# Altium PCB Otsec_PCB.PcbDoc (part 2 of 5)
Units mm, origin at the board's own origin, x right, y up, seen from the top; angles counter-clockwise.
Board outline 170 x 120 mm, 3 copper layers (Top Layer, Internal Plane 1, Bottom Layer), stack 1.608 mm thick; 1624 components, 0 nets, 5478 pads, 0 vias.
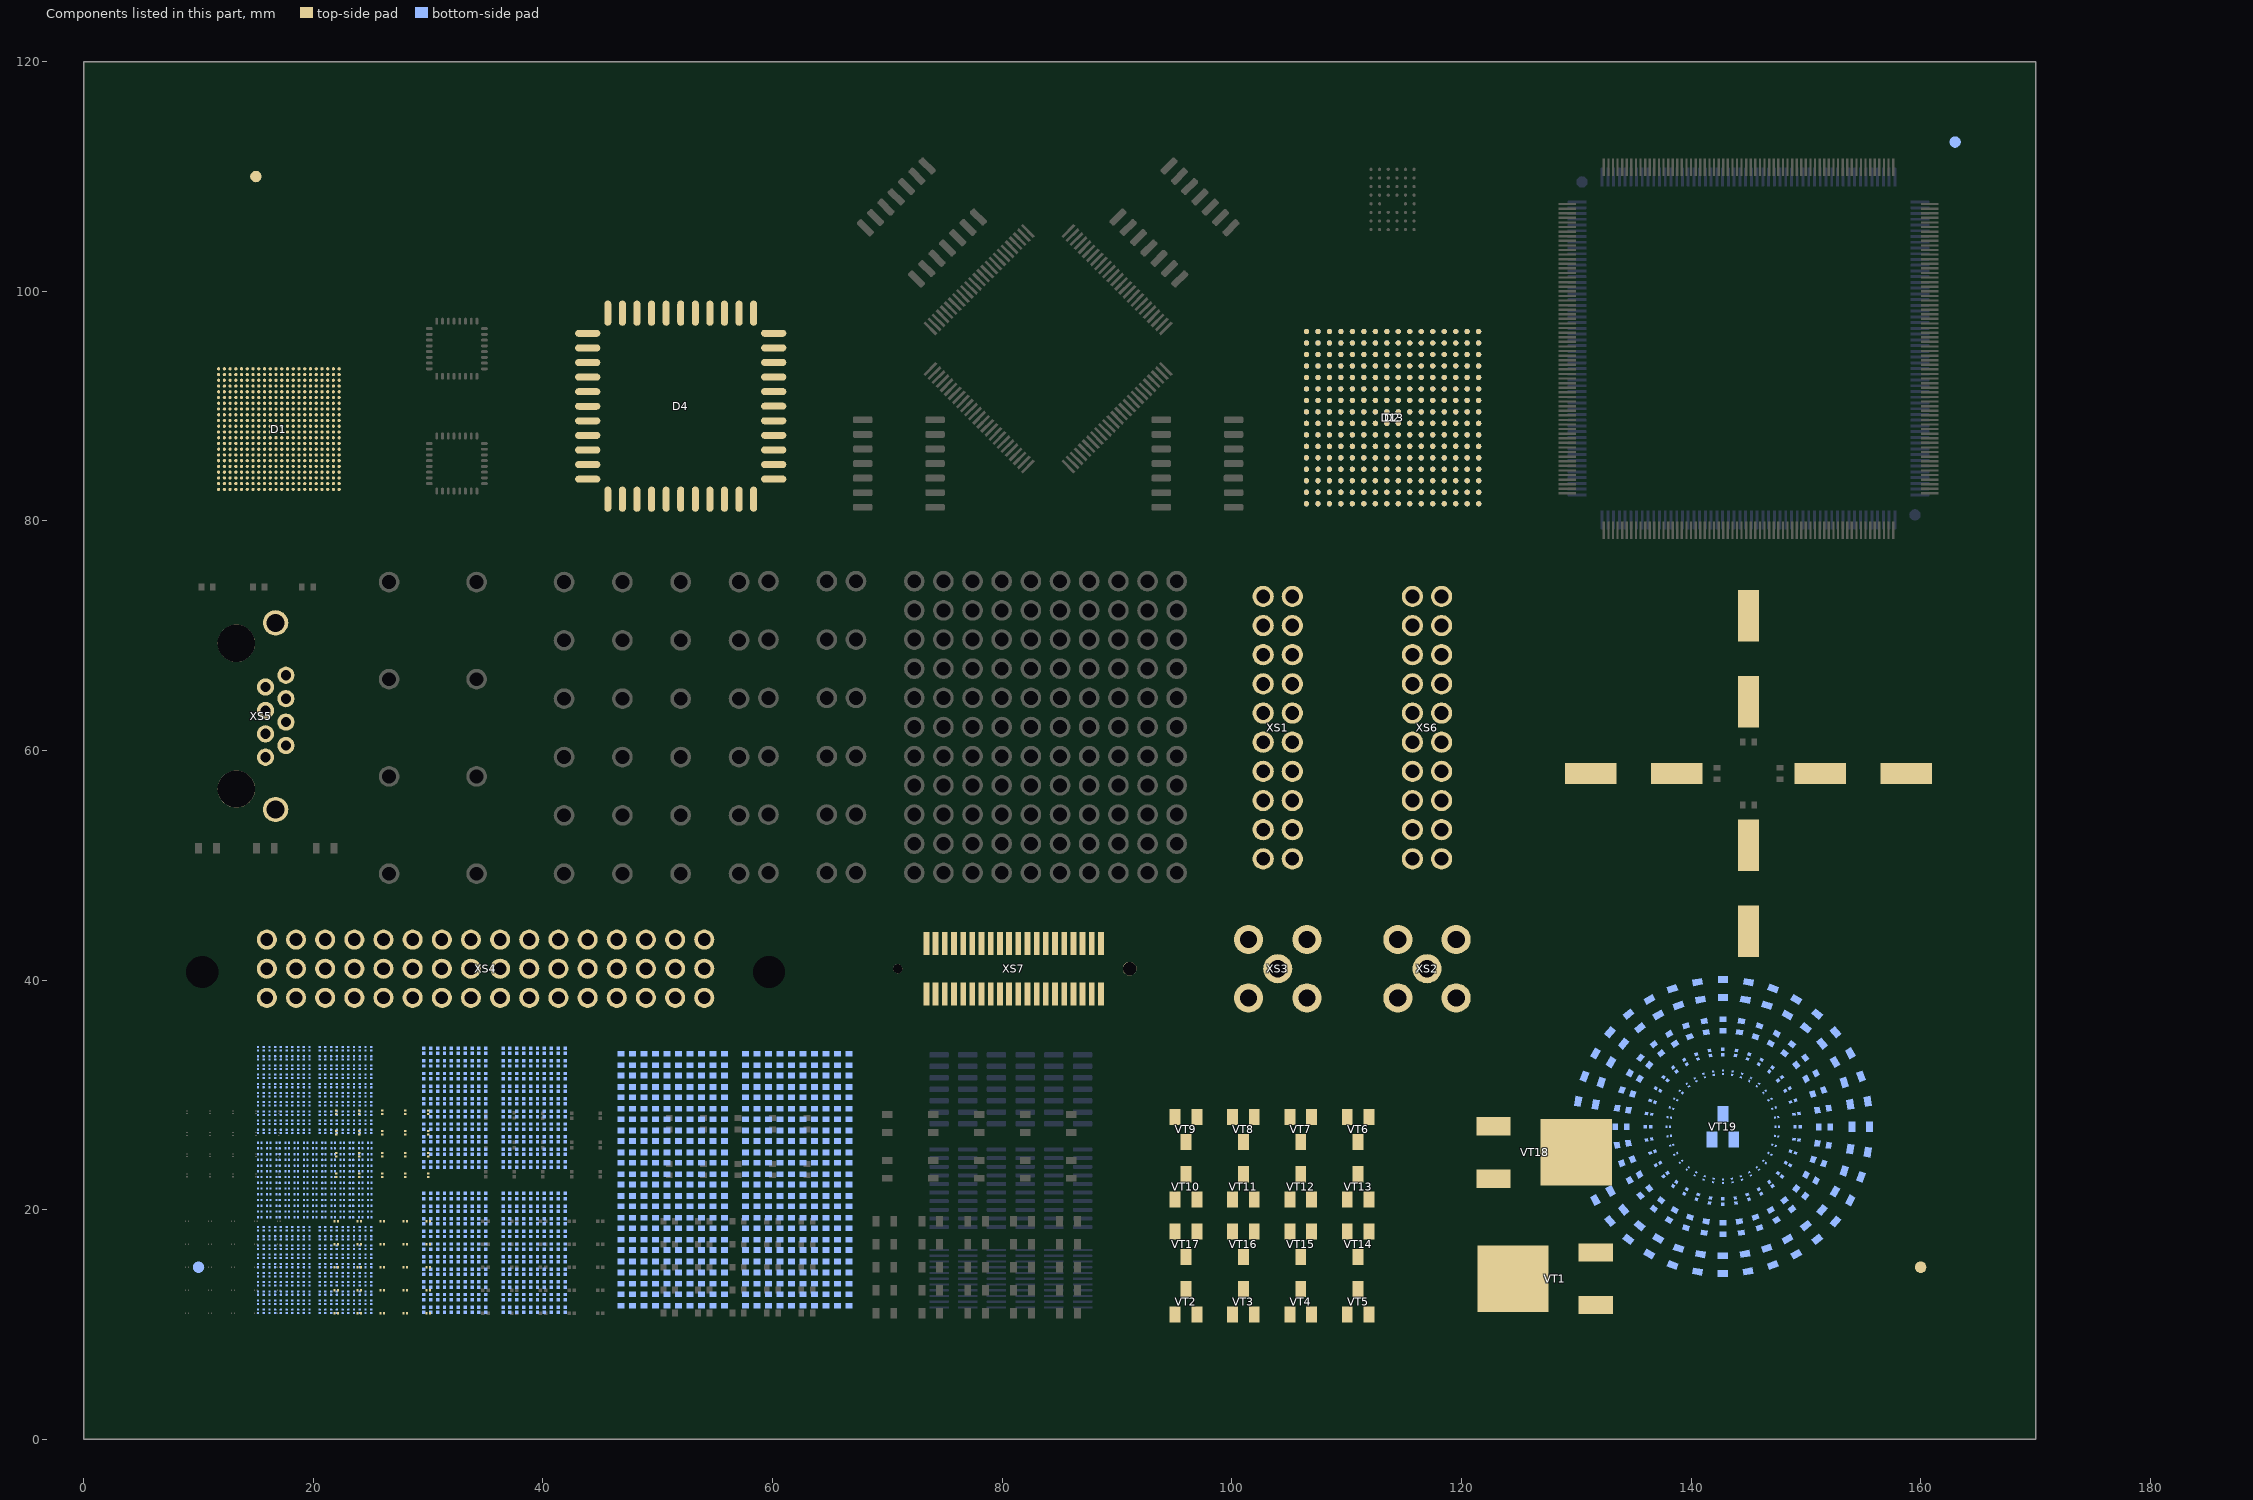
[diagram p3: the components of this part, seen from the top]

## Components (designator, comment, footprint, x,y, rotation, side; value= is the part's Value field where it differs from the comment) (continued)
R375_2 "*" R0201_nosilk 35.025,12.4 r90 bottom
R375_2_1 "*" R0201_nosilk 41.925,12.4 r90 bottom
R376 "*" R0201_nosilk 33.225,32.75 r90 bottom
R376_1 "*" R0201_nosilk 40.125,32.75 r90 bottom
R376_2 "*" R0201_nosilk 33.225,20.1 r90 bottom
R376_2_1 "*" R0201_nosilk 40.125,20.1 r90 bottom
R377 "*" R0201_nosilk 34.425,32.75 r90 bottom
R377_1 "*" R0201_nosilk 41.325,32.75 r90 bottom
R377_2 "*" R0201_nosilk 34.425,20.1 r90 bottom
R377_2_1 "*" R0201_nosilk 41.325,20.1 r90 bottom
R378 "*" R0201_nosilk 31.425,31.65 r90 bottom
R378_1 "*" R0201_nosilk 38.325,31.65 r90 bottom
R378_2 "*" R0201_nosilk 31.425,19 r90 bottom
R378_2_1 "*" R0201_nosilk 38.325,19 r90 bottom
R379 "*" R0201_nosilk 33.825,31.65 r90 bottom
R379_1 "*" R0201_nosilk 40.725,31.65 r90 bottom
R379_2 "*" R0201_nosilk 33.825,19 r90 bottom
R379_2_1 "*" R0201_nosilk 40.725,19 r90 bottom
R380 "*" R0201_nosilk 30.825,30.55 r90 bottom
R380_1 "*" R0201_nosilk 37.725,30.55 r90 bottom
R380_2 "*" R0201_nosilk 30.825,17.9 r90 bottom
R380_2_1 "*" R0201_nosilk 37.725,17.9 r90 bottom
R381 "*" R0201_nosilk 35.025,30.55 r90 bottom
R381_1 "*" R0201_nosilk 41.925,30.55 r90 bottom
R381_2 "*" R0201_nosilk 35.025,17.9 r90 bottom
R381_2_1 "*" R0201_nosilk 41.925,17.9 r90 bottom
R382 "*" R0201_nosilk 29.625,29.45 r90 bottom
R382_1 "*" R0201_nosilk 36.525,29.45 r90 bottom
R382_2 "*" R0201_nosilk 29.625,16.8 r90 bottom
R382_2_1 "*" R0201_nosilk 36.525,16.8 r90 bottom
R383 "*" R0201_nosilk 35.025,23.95 r90 bottom
R383_1 "*" R0201_nosilk 41.925,23.95 r90 bottom
R383_2 "*" R0201_nosilk 35.025,11.3 r90 bottom
R383_2_1 "*" R0201_nosilk 41.925,11.3 r90 bottom
R384 "*" R0201_nosilk 32.025,23.95 r90 bottom
R384_1 "*" R0201_nosilk 38.925,23.95 r90 bottom
R384_2 "*" R0201_nosilk 32.025,11.3 r90 bottom
R384_2_1 "*" R0201_nosilk 38.925,11.3 r90 bottom
R385 "*" R0201_nosilk 29.625,23.95 r90 bottom
R385_1 "*" R0201_nosilk 36.525,23.95 r90 bottom
R385_2 "*" R0201_nosilk 29.625,11.3 r90 bottom
R385_2_1 "*" R0201_nosilk 36.525,11.3 r90 bottom
R386 "*" R0201_nosilk 30.225,31.65 r90 bottom
R386_1 "*" R0201_nosilk 37.125,31.65 r90 bottom
R386_2 "*" R0201_nosilk 30.225,19 r90 bottom
R386_2_1 "*" R0201_nosilk 37.125,19 r90 bottom
R387 "*" R0201_nosilk 32.025,31.65 r90 bottom
R387_1 "*" R0201_nosilk 38.925,31.65 r90 bottom
R387_2 "*" R0201_nosilk 32.025,19 r90 bottom
R387_2_1 "*" R0201_nosilk 38.925,19 r90 bottom
R388 "*" R0201_nosilk 32.625,31.65 r90 bottom
R388_1 "*" R0201_nosilk 39.525,31.65 r90 bottom
R388_2 "*" R0201_nosilk 32.625,19 r90 bottom
R388_2_1 "*" R0201_nosilk 39.525,19 r90 bottom
R389 "*" R0201_nosilk 32.625,30.55 r90 bottom
R389_1 "*" R0201_nosilk 39.525,30.55 r90 bottom
R389_2 "*" R0201_nosilk 32.625,17.9 r90 bottom
R389_2_1 "*" R0201_nosilk 39.525,17.9 r90 bottom
R390 "*" R0201_nosilk 33.225,30.55 r90 bottom
R390_1 "*" R0201_nosilk 40.125,30.55 r90 bottom
R390_2 "*" R0201_nosilk 33.225,17.9 r90 bottom
R390_2_1 "*" R0201_nosilk 40.125,17.9 r90 bottom
R391 "*" R0201_nosilk 30.225,29.45 r90 bottom
R391_1 "*" R0201_nosilk 37.125,29.45 r90 bottom
R391_2 "*" R0201_nosilk 30.225,16.8 r90 bottom
R391_2_1 "*" R0201_nosilk 37.125,16.8 r90 bottom
R392 "*" R0201_nosilk 32.625,29.45 r90 bottom
R392_1 "*" R0201_nosilk 39.525,29.45 r90 bottom
R392_2 "*" R0201_nosilk 32.625,16.8 r90 bottom
R392_2_1 "*" R0201_nosilk 39.525,16.8 r90 bottom
R393 "*" R0201_nosilk 34.425,23.95 r90 bottom
R393_1 "*" R0201_nosilk 41.325,23.95 r90 bottom
R393_2 "*" R0201_nosilk 34.425,11.3 r90 bottom
R393_2_1 "*" R0201_nosilk 41.325,11.3 r90 bottom
R394 "*" R0201_nosilk 32.625,23.95 r90 bottom
R394_1 "*" R0201_nosilk 39.525,23.95 r90 bottom
R394_2 "*" R0201_nosilk 32.625,11.3 r90 bottom
R394_2_1 "*" R0201_nosilk 39.525,11.3 r90 bottom
R395 "*" R0201_nosilk 31.425,23.95 r90 bottom
R395_1 "*" R0201_nosilk 38.325,23.95 r90 bottom
R395_2 "*" R0201_nosilk 31.425,11.3 r90 bottom
R395_2_1 "*" R0201_nosilk 38.325,11.3 r90 bottom
R396 "*" R0201_nosilk 33.825,32.75 r90 bottom
R396_1 "*" R0201_nosilk 40.725,32.75 r90 bottom
R396_2 "*" R0201_nosilk 33.825,20.1 r90 bottom
R396_2_1 "*" R0201_nosilk 40.725,20.1 r90 bottom
R397 "*" R0201_nosilk 34.425,31.65 r90 bottom
R397_1 "*" R0201_nosilk 41.325,31.65 r90 bottom
R397_2 "*" R0201_nosilk 34.425,19 r90 bottom
R397_2_1 "*" R0201_nosilk 41.325,19 r90 bottom
R398 "*" R0201_nosilk 35.025,31.65 r90 bottom
R398_1 "*" R0201_nosilk 41.925,31.65 r90 bottom
R398_2 "*" R0201_nosilk 35.025,19 r90 bottom
R398_2_1 "*" R0201_nosilk 41.925,19 r90 bottom
R399 "*" R0201_nosilk 33.825,30.55 r90 bottom
R399_1 "*" R0201_nosilk 40.725,30.55 r90 bottom
R399_2 "*" R0201_nosilk 33.825,17.9 r90 bottom
R399_2_1 "*" R0201_nosilk 40.725,17.9 r90 bottom
R400 "*" R0201_nosilk 34.425,30.55 r90 bottom
R400_1 "*" R0201_nosilk 41.325,30.55 r90 bottom
R400_2 "*" R0201_nosilk 34.425,17.9 r90 bottom
R400_2_1 "*" R0201_nosilk 41.325,17.9 r90 bottom
R401 "*" R0201_nosilk 31.425,29.45 r90 bottom
R401_1 "*" R0201_nosilk 38.325,29.45 r90 bottom
R401_2 "*" R0201_nosilk 31.425,16.8 r90 bottom
R401_2_1 "*" R0201_nosilk 38.325,16.8 r90 bottom
R402 "*" R0201_nosilk 32.025,29.45 r90 bottom
R402_1 "*" R0201_nosilk 38.925,29.45 r90 bottom
R402_2 "*" R0201_nosilk 32.025,16.8 r90 bottom
R402_2_1 "*" R0201_nosilk 38.925,16.8 r90 bottom
R403 "*" R0201_nosilk 33.825,23.95 r90 bottom
R403_1 "*" R0201_nosilk 40.725,23.95 r90 bottom
R403_2 "*" R0201_nosilk 33.825,11.3 r90 bottom
R403_2_1 "*" R0201_nosilk 40.725,11.3 r90 bottom
R404 "*" R0201_nosilk 33.225,23.95 r90 bottom
R404_1 "*" R0201_nosilk 40.125,23.95 r90 bottom
R404_2 "*" R0201_nosilk 33.225,11.3 r90 bottom
R404_2_1 "*" R0201_nosilk 40.125,11.3 r90 bottom
R405 "*" R0201_nosilk 30.825,23.95 r90 bottom
R405_1 "*" R0201_nosilk 37.725,23.95 r90 bottom
R405_2 "*" R0201_nosilk 30.825,11.3 r90 bottom
R405_2_1 "*" R0201_nosilk 37.725,11.3 r90 bottom
R406 "*" R0201_nosilk 35.025,32.75 r90 bottom
R406_1 "*" R0201_nosilk 41.925,32.75 r90 bottom
R406_2 "*" R0201_nosilk 35.025,20.1 r90 bottom
R406_2_1 "*" R0201_nosilk 41.925,20.1 r90 bottom
R407 "*" R0201_nosilk 29.625,30.55 r90 bottom
R407_1 "*" R0201_nosilk 36.525,30.55 r90 bottom
R407_2 "*" R0201_nosilk 29.625,17.9 r90 bottom
R407_2_1 "*" R0201_nosilk 36.525,17.9 r90 bottom
R408 "*" R0201_nosilk 30.225,30.55 r90 bottom
R408_1 "*" R0201_nosilk 37.125,30.55 r90 bottom
R408_2 "*" R0201_nosilk 30.225,17.9 r90 bottom
R408_2_1 "*" R0201_nosilk 37.125,17.9 r90 bottom
R409 "*" R0201_nosilk 32.625,32.75 r90 bottom
R409_1 "*" R0201_nosilk 39.525,32.75 r90 bottom
R409_2 "*" R0201_nosilk 32.625,20.1 r90 bottom
R409_2_1 "*" R0201_nosilk 39.525,20.1 r90 bottom
R410 "*" R0201_nosilk 30.825,29.45 r90 bottom
R410_1 "*" R0201_nosilk 37.725,29.45 r90 bottom
R410_2 "*" R0201_nosilk 30.825,16.8 r90 bottom
R410_2_1 "*" R0201_nosilk 37.725,16.8 r90 bottom
R411 "*" R0402_NOSILK 54.8,23.6 r90 bottom
R411_1 "*" R0402_NOSILK 65.65,23.6 r90 bottom
R412 "*" R0402_NOSILK 47.8,21.7 r90 bottom
R412_1 "*" R0402_NOSILK 58.65,21.7 r90 bottom
R413 "*" R0402_NOSILK 50.8,25.5 r90 bottom
R413_1 "*" R0402_NOSILK 61.65,25.5 r90 bottom
R414 "*" R0402_NOSILK 53.8,25.5 r90 bottom
R414_1 "*" R0402_NOSILK 64.65,25.5 r90 bottom
R415 "*" R0402_NOSILK 48.8,23.6 r90 bottom
R415_1 "*" R0402_NOSILK 59.65,23.6 r90 bottom
R416 "*" R0402_NOSILK 53.8,23.6 r90 bottom
R416_1 "*" R0402_NOSILK 64.65,23.6 r90 bottom
R417 "*" R0402_NOSILK 51.8,19.8 r90 bottom
R417_1 "*" R0402_NOSILK 62.65,19.8 r90 bottom
R418 "*" R0402_NOSILK 53.8,16 r90 bottom
R418_1 "*" R0402_NOSILK 64.65,16 r90 bottom
R418_1_1 "*" R0402_NOSILK 64.65,12.15 r90 bottom
R418_2 "*" R0402_NOSILK 53.8,12.15 r90 bottom
R419 "*" R0402_NOSILK 49.8,31.2 r90 bottom
R419_1 "*" R0402_NOSILK 60.65,31.2 r90 bottom
R420 "*" R0402_NOSILK 48.8,29.3 r90 bottom
R420_1 "*" R0402_NOSILK 59.65,29.3 r90 bottom
R421 "*" R0402_NOSILK 52.8,31.2 r90 bottom
R421_1 "*" R0402_NOSILK 63.65,31.2 r90 bottom
R422 "*" R0402_NOSILK 46.8,17.9 r90 bottom
R422_1 "*" R0402_NOSILK 57.65,17.9 r90 bottom
R422_1_1 "*" R0402_NOSILK 57.65,14.05 r90 bottom
R422_2 "*" R0402_NOSILK 46.8,14.05 r90 bottom
R423 "*" R0402_NOSILK 52.8,17.9 r90 bottom
R423_1 "*" R0402_NOSILK 63.65,17.9 r90 bottom
R423_1_1 "*" R0402_NOSILK 63.65,14.05 r90 bottom
R423_2 "*" R0402_NOSILK 52.8,14.05 r90 bottom
R424 "*" R0402_NOSILK 47.8,27.4 r90 bottom
R424_1 "*" R0402_NOSILK 58.65,27.4 r90 bottom
R425 "*" R0402_NOSILK 53.8,27.4 r90 bottom
R425_1 "*" R0402_NOSILK 64.65,27.4 r90 bottom
R426 "*" R0402_NOSILK 47.8,16 r90 bottom
R426_1 "*" R0402_NOSILK 58.65,16 r90 bottom
R426_1_1 "*" R0402_NOSILK 58.65,12.15 r90 bottom
R426_2 "*" R0402_NOSILK 47.8,12.15 r90 bottom
R427 "*" R0402_NOSILK 50.8,16 r90 bottom
R427_1 "*" R0402_NOSILK 61.65,16 r90 bottom
R427_1_1 "*" R0402_NOSILK 61.65,12.15 r90 bottom
R427_2 "*" R0402_NOSILK 50.8,12.15 r90 bottom
R428 "*" R0402_NOSILK 46.8,25.5 r90 bottom
R428_1 "*" R0402_NOSILK 57.65,25.5 r90 bottom
R429 "*" R0402_NOSILK 49.8,25.5 r90 bottom
R429_1 "*" R0402_NOSILK 60.65,25.5 r90 bottom
R430 "*" R0402_NOSILK 51.8,33.1 r90 bottom
R430_1 "*" R0402_NOSILK 62.65,33.1 r90 bottom
R431 "*" R0402_NOSILK 48.8,21.7 r90 bottom
R431_1 "*" R0402_NOSILK 59.65,21.7 r90 bottom
R432 "*" R0402_NOSILK 51.8,21.7 r90 bottom
R432_1 "*" R0402_NOSILK 62.65,21.7 r90 bottom
R433 "*" R0402_NOSILK 54.8,19.8 r90 bottom
R433_1 "*" R0402_NOSILK 65.65,19.8 r90 bottom
R434 "*" R0402_NOSILK 46.8,31.2 r90 bottom
R434_1 "*" R0402_NOSILK 57.65,31.2 r90 bottom
R435 "*" R0402_NOSILK 46.8,29.3 r90 bottom
R435_1 "*" R0402_NOSILK 57.65,29.3 r90 bottom
R436 "*" R0402_NOSILK 55.8,33.1 r90 bottom
R436_1 "*" R0402_NOSILK 66.65,33.1 r90 bottom
R437 "*" R0402_NOSILK 49.8,23.6 r90 bottom
R437_1 "*" R0402_NOSILK 60.65,23.6 r90 bottom
R438 "*" R0402_NOSILK 52.8,23.6 r90 bottom
R438_1 "*" R0402_NOSILK 63.65,23.6 r90 bottom
R439 "*" R0402_NOSILK 54.8,29.3 r90 bottom
R439_1 "*" R0402_NOSILK 65.65,29.3 r90 bottom
R440 "*" R0402_NOSILK 50.8,27.4 r90 bottom
R440_1 "*" R0402_NOSILK 61.65,27.4 r90 bottom
R441 "*" R0402_NOSILK 52.8,16 r90 bottom
R441_1 "*" R0402_NOSILK 63.65,16 r90 bottom
R441_1_1 "*" R0402_NOSILK 63.65,12.15 r90 bottom
R441_2 "*" R0402_NOSILK 52.8,12.15 r90 bottom
R442 "*" R0402_NOSILK 48.8,25.5 r90 bottom
R442_1 "*" R0402_NOSILK 59.65,25.5 r90 bottom
R443 "*" R0402_NOSILK 54.8,25.5 r90 bottom
R443_1 "*" R0402_NOSILK 65.65,25.5 r90 bottom
R444 "*" R0402_NOSILK 47.8,33.1 r90 bottom
R444_1 "*" R0402_NOSILK 58.65,33.1 r90 bottom
R445 "*" R0402_NOSILK 48.8,33.1 r90 bottom
R445_1 "*" R0402_NOSILK 59.65,33.1 r90 bottom
R446 "*" R0402_NOSILK 47.8,19.8 r90 bottom
R446_1 "*" R0402_NOSILK 58.65,19.8 r90 bottom
R447 "*" R0402_NOSILK 46.8,16 r90 bottom
R447_1 "*" R0402_NOSILK 57.65,16 r90 bottom
R447_1_1 "*" R0402_NOSILK 57.65,12.15 r90 bottom
R447_2 "*" R0402_NOSILK 46.8,12.15 r90 bottom
R448 "*" R0402_NOSILK 48.8,31.2 r90 bottom
R448_1 "*" R0402_NOSILK 59.65,31.2 r90 bottom
R449 "*" R0402_NOSILK 51.8,29.3 r90 bottom
R449_1 "*" R0402_NOSILK 62.65,29.3 r90 bottom
R450 "*" R0402_NOSILK 49.8,16 r90 bottom
R450_1 "*" R0402_NOSILK 60.65,16 r90 bottom
R450_1_1 "*" R0402_NOSILK 60.65,12.15 r90 bottom
R450_2 "*" R0402_NOSILK 49.8,12.15 r90 bottom
R451 "*" R0402_NOSILK 51.8,23.6 r90 bottom
R451_1 "*" R0402_NOSILK 62.65,23.6 r90 bottom
R452 "*" R0402_NOSILK 51.8,17.9 r90 bottom
R452_1 "*" R0402_NOSILK 62.65,17.9 r90 bottom
R452_1_1 "*" R0402_NOSILK 62.65,14.05 r90 bottom
R452_2 "*" R0402_NOSILK 51.8,14.05 r90 bottom
R453 "*" R0402_NOSILK 46.8,27.4 r90 bottom
R453_1 "*" R0402_NOSILK 57.65,27.4 r90 bottom
R454 "*" R0402_NOSILK 52.8,27.4 r90 bottom
R454_1 "*" R0402_NOSILK 63.65,27.4 r90 bottom
R455 "*" R0402_NOSILK 50.8,21.7 r90 bottom
R455_1 "*" R0402_NOSILK 61.65,21.7 r90 bottom
R456 "*" R0402_NOSILK 55.8,25.5 r90 bottom
R456_1 "*" R0402_NOSILK 66.65,25.5 r90 bottom
R457 "*" R0402_NOSILK 48.8,19.8 r90 bottom
R457_1 "*" R0402_NOSILK 59.65,19.8 r90 bottom
R458 "*" R0402_NOSILK 46.8,33.1 r90 bottom
R458_1 "*" R0402_NOSILK 57.65,33.1 r90 bottom
R459 "*" R0402_NOSILK 50.8,33.1 r90 bottom
R459_1 "*" R0402_NOSILK 61.65,33.1 r90 bottom
R460 "*" R0402_NOSILK 54.8,31.2 r90 bottom
R460_1 "*" R0402_NOSILK 65.65,31.2 r90 bottom
R461 "*" R0402_NOSILK 47.8,31.2 r90 bottom
R461_1 "*" R0402_NOSILK 58.65,31.2 r90 bottom
R462 "*" R0402_NOSILK 49.8,29.3 r90 bottom
R462_1 "*" R0402_NOSILK 60.65,29.3 r90 bottom
R463 "*" R0402_NOSILK 48.8,16 r90 bottom
R463_1 "*" R0402_NOSILK 59.65,16 r90 bottom
R463_1_1 "*" R0402_NOSILK 59.65,12.15 r90 bottom
R463_2 "*" R0402_NOSILK 48.8,12.15 r90 bottom
R464 "*" R0402_NOSILK 51.8,16 r90 bottom
R464_1 "*" R0402_NOSILK 62.65,16 r90 bottom
R464_1_1 "*" R0402_NOSILK 62.65,12.15 r90 bottom
R464_2 "*" R0402_NOSILK 51.8,12.15 r90 bottom
R465 "*" R0402_NOSILK 47.8,25.5 r90 bottom
R465_1 "*" R0402_NOSILK 58.65,25.5 r90 bottom
R466 "*" R0402_NOSILK 55.8,29.3 r90 bottom
R466_1 "*" R0402_NOSILK 66.65,29.3 r90 bottom
R467 "*" R0402_NOSILK 51.8,27.4 r90 bottom
R467_1 "*" R0402_NOSILK 62.65,27.4 r90 bottom
R468 "*" R0402_NOSILK 49.8,21.7 r90 bottom
R468_1 "*" R0402_NOSILK 60.65,21.7 r90 bottom
R469 "*" R0402_NOSILK 46.8,19.8 r90 bottom
R469_1 "*" R0402_NOSILK 57.65,19.8 r90 bottom
R470 "*" R0402_NOSILK 55.8,19.8 r90 bottom
R470_1 "*" R0402_NOSILK 66.65,19.8 r90 bottom
R471 "*" R0402_NOSILK 49.8,19.8 r90 bottom
R471_1 "*" R0402_NOSILK 60.65,19.8 r90 bottom
R472 "*" R0402_NOSILK 49.8,33.1 r90 bottom
R472_1 "*" R0402_NOSILK 60.65,33.1 r90 bottom
R473 "*" R0402_NOSILK 53.8,31.2 r90 bottom
R473_1 "*" R0402_NOSILK 64.65,31.2 r90 bottom
R474 "*" R0402_NOSILK 50.8,23.6 r90 bottom
R474_1 "*" R0402_NOSILK 61.65,23.6 r90 bottom
R475 "*" R0402_NOSILK 50.8,17.9 r90 bottom
R475_1 "*" R0402_NOSILK 61.65,17.9 r90 bottom
R475_1_1 "*" R0402_NOSILK 61.65,14.05 r90 bottom
R475_2 "*" R0402_NOSILK 50.8,14.05 r90 bottom
R476 "*" R0402_NOSILK 52.8,29.3 r90 bottom
R476_1 "*" R0402_NOSILK 63.65,29.3 r90 bottom
R477 "*" R0402_NOSILK 55.8,23.6 r90 bottom
R477_1 "*" R0402_NOSILK 66.65,23.6 r90 bottom
R478 "*" R0402_NOSILK 52.8,21.7 r90 bottom
R478_1 "*" R0402_NOSILK 63.65,21.7 r90 bottom
R479 "*" R0402_NOSILK 51.8,25.5 r90 bottom
R479_1 "*" R0402_NOSILK 62.65,25.5 r90 bottom
R480 "*" R0402_NOSILK 46.8,23.6 r90 bottom
R480_1 "*" R0402_NOSILK 57.65,23.6 r90 bottom
R481 "*" R0402_NOSILK 54.8,27.4 r90 bottom
R481_1 "*" R0402_NOSILK 65.65,27.4 r90 bottom
R482 "*" R0402_NOSILK 54.8,21.7 r90 bottom
R482_1 "*" R0402_NOSILK 65.65,21.7 r90 bottom
R483 "*" R0402_NOSILK 52.8,19.8 r90 bottom
R483_1 "*" R0402_NOSILK 63.65,19.8 r90 bottom
R484 "*" R0402_NOSILK 54.8,16 r90 bottom
R484_1 "*" R0402_NOSILK 65.65,16 r90 bottom
R484_1_1 "*" R0402_NOSILK 65.65,12.15 r90 bottom
R484_2 "*" R0402_NOSILK 54.8,12.15 r90 bottom
R485 "*" R0402_NOSILK 50.8,31.2 r90 bottom
R485_1 "*" R0402_NOSILK 61.65,31.2 r90 bottom
R486 "*" R0402_NOSILK 52.8,33.1 r90 bottom
R486_1 "*" R0402_NOSILK 63.65,33.1 r90 bottom
R487 "*" R0402_NOSILK 55.8,31.2 r90 bottom
R487_1 "*" R0402_NOSILK 66.65,31.2 r90 bottom
R488 "*" R0402_NOSILK 48.8,17.9 r90 bottom
R488_1 "*" R0402_NOSILK 59.65,17.9 r90 bottom
R488_1_1 "*" R0402_NOSILK 59.65,14.05 r90 bottom
R488_2 "*" R0402_NOSILK 48.8,14.05 r90 bottom
R489 "*" R0402_NOSILK 53.8,17.9 r90 bottom
R489_1 "*" R0402_NOSILK 64.65,17.9 r90 bottom
R489_1_1 "*" R0402_NOSILK 64.65,14.05 r90 bottom
R489_2 "*" R0402_NOSILK 53.8,14.05 r90 bottom
R490 "*" R0402_NOSILK 48.8,27.4 r90 bottom
R490_1 "*" R0402_NOSILK 59.65,27.4 r90 bottom
R491 "*" R0402_NOSILK 46.8,21.7 r90 bottom
R491_1 "*" R0402_NOSILK 57.65,21.7 r90 bottom
R492 "*" R0402_NOSILK 53.8,21.7 r90 bottom
R492_1 "*" R0402_NOSILK 64.65,21.7 r90 bottom
R493 "*" R0402_NOSILK 52.8,25.5 r90 bottom
R493_1 "*" R0402_NOSILK 63.65,25.5 r90 bottom
R494 "*" R0402_NOSILK 47.8,23.6 r90 bottom
R494_1 "*" R0402_NOSILK 58.65,23.6 r90 bottom
R495 "*" R0402_NOSILK 50.8,19.8 r90 bottom
R495_1 "*" R0402_NOSILK 61.65,19.8 r90 bottom
R496 "*" R0402_NOSILK 55.8,21.7 r90 bottom
R496_1 "*" R0402_NOSILK 66.65,21.7 r90 bottom
R497 "*" R0402_NOSILK 53.8,19.8 r90 bottom
R497_1 "*" R0402_NOSILK 64.65,19.8 r90 bottom
R498 "*" R0402_NOSILK 55.8,16 r90 bottom
R498_1 "*" R0402_NOSILK 66.65,16 r90 bottom
R498_1_1 "*" R0402_NOSILK 66.65,12.15 r90 bottom
R498_2 "*" R0402_NOSILK 55.8,12.15 r90 bottom
R499 "*" R0402_NOSILK 51.8,31.2 r90 bottom
R499_1 "*" R0402_NOSILK 62.65,31.2 r90 bottom
R500 "*" R0402_NOSILK 53.8,29.3 r90 bottom
R500_1 "*" R0402_NOSILK 64.65,29.3 r90 bottom
R501 "*" R0402_NOSILK 47.8,29.3 r90 bottom
R501_1 "*" R0402_NOSILK 58.65,29.3 r90 bottom
R502 "*" R0402_NOSILK 47.8,17.9 r90 bottom
R502_1 "*" R0402_NOSILK 58.65,17.9 r90 bottom
R502_1_1 "*" R0402_NOSILK 58.65,14.05 r90 bottom
R502_2 "*" R0402_NOSILK 47.8,14.05 r90 bottom
R503 "*" R0402_NOSILK 54.8,17.9 r90 bottom
R503_1 "*" R0402_NOSILK 65.65,17.9 r90 bottom
R503_1_1 "*" R0402_NOSILK 65.65,14.05 r90 bottom
R503_2 "*" R0402_NOSILK 54.8,14.05 r90 bottom
R504 "*" R0402_NOSILK 49.8,27.4 r90 bottom
R504_1 "*" R0402_NOSILK 60.65,27.4 r90 bottom
R505 "*" R0402_NOSILK 55.8,27.4 r90 bottom
R505_1 "*" R0402_NOSILK 66.65,27.4 r90 bottom
R506 "*" R0402_NOSILK 54.8,33.1 r90 bottom
R506_1 "*" R0402_NOSILK 65.65,33.1 r90 bottom
R507 "*" R0402_NOSILK 50.8,29.3 r90 bottom
R507_1 "*" R0402_NOSILK 61.65,29.3 r90 bottom
R508 "*" R0402_NOSILK 49.8,17.9 r90 bottom
R508_1 "*" R0402_NOSILK 60.65,17.9 r90 bottom
R508_1_1 "*" R0402_NOSILK 60.65,14.05 r90 bottom
R508_2 "*" R0402_NOSILK 49.8,14.05 r90 bottom
R509 "*" R0402_NOSILK 55.8,17.9 r90 bottom
R509_1 "*" R0402_NOSILK 66.65,17.9 r90 bottom
R509_1_1 "*" R0402_NOSILK 66.65,14.05 r90 bottom
R509_2 "*" R0402_NOSILK 55.8,14.05 r90 bottom
R510 "*" R0402_NOSILK 53.8,33.1 r90 bottom
R510_1 "*" R0402_NOSILK 64.65,33.1 r90 bottom
R511 "*" R01005 145.144,31.35 r60 bottom
R512 "*" R01005 146.875,29.605 r30 bottom
R513 "*" R01005 144.382,22.775 r290 bottom
R514 "*" R01005 141.135,31.7 r110 bottom
R515 "*" R01005 146.4,30.279 r40 bottom
R516 "*" R01005 143.584,22.55 r280 bottom
R517 "*" R01005 141.947,31.9 r100 bottom
R518 "*" R01005 147.225,28.858 r20 bottom
R519 "*" R01005 142.775,31.975 r90 bottom
R520 "*" R01005 147.508,27.233 r0 bottom
R521 "*" R01005 145.821,30.875 r50 bottom
R522 "*" R01005 144.39,31.7 r70 bottom
R523 "*" R01005 147.45,28.057 r10 bottom
R524 "*" R01005 143.593,31.9 r80 bottom
R525 "*" R01005 138.65,29.612 r150 bottom
R526 "*" R01005 138.3,28.862 r160 bottom
R527 "*" R01005 140.4,31.338 r120 bottom
R528 "*" R01005 139.725,30.863 r130 bottom
R529 "*" R01005 139.137,30.275 r140 bottom
R530 "*" R01005 142.775,22.5 r270 bottom
R531 "*" R01005 145.134,23.125 r300 bottom
R532 "*" R01005 147.225,25.615 r340 bottom
R533 "*" R01005 147.45,26.413 r350 bottom
R534 "*" R01005 146.875,24.875 r330 bottom
R535 "*" R01005 138.309,25.625 r200 bottom
R536 "*" R01005 139.712,23.6 r230 bottom
R537 "*" R01005 138.656,24.875 r210 bottom
R538 "*" R01005 138.1,28.054 r170 bottom
R539 "*" R01005 140.391,23.125 r240 bottom
R540 "*" R01005 146.4,24.175 r320 bottom
R541 "*" R01005 138.025,27.233 r180 bottom
R542 "*" R01005 138.1,26.425 r190 bottom
R543 "*" R01005 139.125,24.186 r220 bottom
R544 "*" R01005 141.942,22.55 r260 bottom
R545 "*" R01005 145.818,23.6 r310 bottom
R546 "*" R01005 141.145,22.775 r250 bottom
R547 "*" R0201_nosilk 137.125,30.493 r150 bottom
R548 "*" R0201_nosilk 136.25,27.225 r180 bottom
R549 "*" R0201_nosilk 140.545,21.125 r250 bottom
R550 "*" R0201_nosilk 143.886,20.825 r280 bottom
R551 "*" R0201_nosilk 148.4,30.485 r30 bottom
R552 "*" R0201_nosilk 149.175,26.11 r350 bottom
R553 "*" R0201_nosilk 146.95,32.221 r50 bottom
R554 "*" R0201_nosilk 137.775,31.416 r140 bottom
R555 "*" R0201_nosilk 141.638,20.825 r260 bottom
R556 "*" R0201_nosilk 146.013,21.6 r300 bottom
R557 "*" R0201_nosilk 146.952,22.25 r310 bottom
R558 "*" R0201_nosilk 147.748,23.05 r320 bottom
R559 "*" R0201_nosilk 136.35,28.361 r170 bottom
R560 "*" R0201_nosilk 136.35,26.122 r190 bottom
R561 "*" R0201_nosilk 138.577,22.25 r230 bottom
R562 "*" R0201_nosilk 139.51,21.6 r240 bottom
R563 "*" R0201_nosilk 137.775,23.056 r220 bottom
R564 "*" R0201_nosilk 148.425,24 r330 bottom
R565 "*" R0201_nosilk 148.875,25.025 r340 bottom
R566 "*" R0201_nosilk 136.65,29.45 r160 bottom
R567 "*" R0201_nosilk 142.767,33.75 r90 bottom
R568 "*" R0201_nosilk 146.025,32.875 r60 bottom
R569 "*" R0201_nosilk 136.646,25.025 r200 bottom
R570 "*" R0201_nosilk 137.125,24 r210 bottom
R571 "*" R0201_nosilk 140.532,33.35 r110 bottom
R572 "*" R0201_nosilk 138.584,32.225 r130 bottom
R573 "*" R0201_nosilk 139.514,32.875 r120 bottom
R574 "*" R0201_nosilk 141.639,33.65 r100 bottom
R575 "*" R0201_nosilk 143.902,33.65 r80 bottom
R576 "*" R0201_nosilk 144.99,33.35 r70 bottom
R577 "*" R0201_nosilk 147.75,31.411 r40 bottom
R578 "*" R0201_nosilk 148.875,29.459 r20 bottom
R579 "*" R0201_nosilk 144.975,21.125 r290 bottom
R580 "*" R0201_nosilk 142.767,20.725 r270 bottom
R581 "*" R0201_nosilk 149.175,28.36 r10 bottom
R582 "*" R0201_nosilk 149.275,27.225 r0 bottom
R583 "*" R0402_NOSILK 149.55,21.536 r320 bottom
R584 "*" R0402_NOSILK 150.444,22.8 r330 bottom
R585 "*" R0402_NOSILK 151.1,24.209 r340 bottom
R586 "*" R0402_NOSILK 151.5,25.703 r350 bottom
R587 "*" R0402_NOSILK 145.789,35.55 r70 bottom
R588 "*" R0402_NOSILK 137.075,20.463 r230 bottom
R589 "*" R0402_NOSILK 141.228,18.5 r260 bottom
R590 "*" R0402_NOSILK 142.767,18.375 r270 bottom
R591 "*" R0402_NOSILK 144.291,18.5 r280 bottom
R592 "*" R0402_NOSILK 145.786,18.9 r290 bottom
R593 "*" R0402_NOSILK 147.194,19.55 r300 bottom
R594 "*" R0402_NOSILK 148.464,20.45 r310 bottom
R595 "*" R0402_NOSILK 147.2,34.912 r60 bottom
R596 "*" R0402_NOSILK 135.975,21.55 r220 bottom
R597 "*" R0402_NOSILK 138.325,19.551 r240 bottom
R598 "*" R0402_NOSILK 139.736,18.9 r250 bottom
R599 "*" R0402_NOSILK 133.9,27.233 r180 bottom
R600 "*" R0402_NOSILK 134.05,25.723 r190 bottom
R601 "*" R0402_NOSILK 134.429,24.225 r200 bottom
R602 "*" R0402_NOSILK 135.083,22.825 r210 bottom
R603 "*" R0402_NOSILK 148.463,34.025 r50 bottom
R604 "*" R0402_NOSILK 135.1,31.663 r150 bottom
R605 "*" R0402_NOSILK 134.45,30.266 r160 bottom
R606 "*" R0402_NOSILK 134.05,28.765 r170 bottom
R607 "*" R0402_NOSILK 139.725,35.559 r110 bottom
R608 "*" R0402_NOSILK 138.35,34.894 r120 bottom
R609 "*" R0402_NOSILK 137.075,34.025 r130 bottom
R610 "*" R0402_NOSILK 135.975,32.925 r140 bottom
R611 "*" R0402_NOSILK 149.557,32.925 r40 bottom
R612 "*" R0402_NOSILK 144.309,35.95 r80 bottom
R613 "*" R0402_NOSILK 142.767,36.1 r90 bottom
R614 "*" R0402_NOSILK 141.235,35.95 r100 bottom
R615 "*" R0402_NOSILK 151.625,27.225 r0 bottom
R616 "*" R0402_NOSILK 151.075,30.26 r20 bottom
R617 "*" R0402_NOSILK 151.5,28.769 r10 bottom
R618 "*" R0402_NOSILK 150.45,31.65 r30 bottom
R619 "*" R0603_NOSILK 154.05,31.344 r20 bottom
R620 "*" R0603_NOSILK 153.175,33.242 r30 bottom
R621 "*" R0603_NOSILK 151.975,34.95 r40 bottom
R622 "*" R0603_NOSILK 150.477,36.425 r50 bottom
R623 "*" R0603_NOSILK 140.69,39.05 r100 bottom
R624 "*" R0603_NOSILK 138.65,38.501 r110 bottom
R625 "*" R0603_NOSILK 154.75,27.233 r0 bottom
R626 "*" R0603_NOSILK 154.6,29.314 r10 bottom
R627 "*" R0603_NOSILK 148.767,37.625 r60 bottom
R628 "*" R0603_NOSILK 146.871,38.525 r70 bottom
R629 "*" R0603_NOSILK 144.858,39.05 r80 bottom
R630 "*" R0603_NOSILK 142.775,39.25 r90 bottom
R631 "*" R0603_NOSILK 133.558,34.95 r140 bottom
R632 "*" R0603_NOSILK 132.375,33.225 r150 bottom
R633 "*" R0603_NOSILK 131.477,31.35 r160 bottom
R634 "*" R0603_NOSILK 130.95,29.31 r170 bottom
R635 "*" R0603_NOSILK 133.555,19.525 r220 bottom
R636 "*" R0603_NOSILK 135.047,18.05 r230 bottom
R637 "*" R0603_NOSILK 136.775,37.625 r120 bottom
R638 "*" R0603_NOSILK 135.064,36.425 r130 bottom
R639 "*" R0603_NOSILK 130.75,27.233 r180 bottom
R640 "*" R0603_NOSILK 130.925,25.182 r190 bottom
R641 "*" R0603_NOSILK 131.475,23.159 r200 bottom
R642 "*" R0603_NOSILK 132.35,21.257 r210 bottom
R643 "*" R0603_NOSILK 140.7,15.4 r260 bottom
R644 "*" R0603_NOSILK 142.767,15.25 r270 bottom
R645 "*" R0603_NOSILK 144.828,15.425 r280 bottom
R646 "*" R0603_NOSILK 146.85,15.95 r290 bottom
R647 "*" R0603_NOSILK 154.05,23.138 r340 bottom
R648 "*" R0603_NOSILK 154.6,25.16 r350 bottom
R649 "*" R0603_NOSILK 136.763,16.85 r240 bottom
R650 "*" R0603_NOSILK 138.664,15.95 r250 bottom
R651 "*" R0603_NOSILK 148.764,16.825 r300 bottom
R652 "*" R0603_NOSILK 150.475,18.05 r310 bottom
R653 "*" R0603_NOSILK 151.975,19.5 r320 bottom
R654 "*" R0603_NOSILK 153.171,21.225 r330 bottom
VT1 "TO-252-2L" DPAK 126,14 r90 top
VT2 "SOT23 JUMPER" SOT23 96,12 r0 top
VT3 "SOT23 JUMPER" SOT23 101,12 r0 top
VT4 "SOT23 JUMPER" SOT23 106,12 r0 top
VT5 "SOT23 JUMPER" SOT23 111,12 r0 top
VT6 "SOT23 JUMPER" SOT23 111,27 r180 top
VT7 "SOT23 JUMPER" SOT23 106,27 r180 top
VT8 "SOT23 JUMPER" SOT23 101,27 r180 top
VT9 "SOT23 JUMPER" SOT23 96,27 r180 top
VT10 "SOT23 JUMPER" SOT23 96,22 r0 top
VT11 "SOT23 JUMPER" SOT23 101,22 r0 top
VT12 "SOT23 JUMPER" SOT23 106,22 r0 top
VT13 "SOT23 JUMPER" SOT23 111,22 r0 top
VT14 "SOT23 JUMPER" SOT23 111,17 r180 top
VT15 "SOT23 JUMPER" SOT23 106,17 r180 top
VT16 "SOT23 JUMPER" SOT23 101,17 r180 top
VT17 "SOT23 JUMPER" SOT23 96,17 r180 top
VT18 "TO-252-2L" DPAK 128.5,25 r270 top
VT19 "SOT23 JUMPER" SOT23 142.767,27.233 r180 bottom
XS1 "PLD 2x10" "PLD 2x10" 104,62 r270 top
XS2 "UCH_Socket" UCH_Socket 117,41 r0 top
XS3 "UCH_Socket" UCH_Socket 104,41 r0 top
XS4 "DIN41612_16x3" DIN41612 35,41 r180 top
XS5 "RJ-45" RJ-45 8,63 r270 top
XS6 "PLD 2x10" "PLD 2x10" 117,62 r270 top
XS7 "PL40_0.8" PL40_0.8 81,41 r0 top

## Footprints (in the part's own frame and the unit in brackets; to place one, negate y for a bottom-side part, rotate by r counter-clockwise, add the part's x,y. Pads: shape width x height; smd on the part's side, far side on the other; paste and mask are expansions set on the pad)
"AluCAP 8x10" [mm]
  rect 4.5x1.8 smd: 1(-3.75,0) 2(3.75,0)
  silkscreen extent -6,-4.5 4.5,4.5, body extent -4.55,-4.15 4.55,4.15, height 10.4
BGA256 [mm]
  round 0.46 smd: 1(-7.5,7.5) 2(-6.5,7.5) 3(-5.5,7.5) 4(-4.5,7.5) 5(-3.5,7.5) 6(-2.5,7.5) 7(-1.5,7.5) 8(-0.5,7.5) 9(0.5,7.5) 10(1.5,7.5) 11(2.5,7.5) 12(3.5,7.5) 13(4.5,7.5) 14(5.5,7.5) 15(6.5,7.5) 16(7.5,7.5) 17(-7.5,6.5) 18(-6.5,6.5) 19(-5.5,6.5) 20(-4.5,6.5) 21(-3.5,6.5) 22(-2.5,6.5) 23(-1.5,6.5) 24(-0.5,6.5) 25(0.5,6.5) 26(1.5,6.5) 27(2.5,6.5) 28(3.5,6.5) 29(4.5,6.5) 30(5.5,6.5) 31(6.5,6.5) 32(7.5,6.5) 33(-7.5,5.5) 34(-6.5,5.5) 35(-5.5,5.5) 36(-4.5,5.5) 37(-3.5,5.5) 38(-2.5,5.5) 39(-1.5,5.5) 40(-0.5,5.5) 41(0.5,5.5) 42(1.5,5.5) 43(2.5,5.5) 44(3.5,5.5) 45(4.5,5.5) 46(5.5,5.5) 47(6.5,5.5) 48(7.5,5.5) 49(-7.5,4.5) 50(-6.5,4.5) 51(-5.5,4.5) 52(-4.5,4.5) 53(-3.5,4.5) 54(-2.5,4.5) 55(-1.5,4.5) 56(-0.5,4.5) 57(0.5,4.5) 58(1.5,4.5) 59(2.5,4.5) 60(3.5,4.5) 61(4.5,4.5) 62(5.5,4.5) 63(6.5,4.5) 64(7.5,4.5) 65(-7.5,3.5) 66(-6.5,3.5) 67(-5.5,3.5) 68(-4.5,3.5) 69(-3.5,3.5) 70(-2.5,3.5) 71(-1.5,3.5) 72(-0.5,3.5) 73(0.5,3.5) 74(1.5,3.5) 75(2.5,3.5) 76(3.5,3.5) 77(4.5,3.5) 78(5.5,3.5) 79(6.5,3.5) 80(7.5,3.5) 81(-7.5,2.5) 82(-6.5,2.5) 83(-5.5,2.5) 84(-4.5,2.5) 85(-3.5,2.5) 86(-2.5,2.5) 87(-1.5,2.5) 88(-0.5,2.5) 89(0.5,2.5) 90(1.5,2.5) 91(2.5,2.5) 92(3.5,2.5) 93(4.5,2.5) 94(5.5,2.5) 95(6.5,2.5) 96(7.5,2.5) 97(-7.5,1.5) 98(-6.5,1.5) 99(-5.5,1.5) 100(-4.5,1.5) 101(-3.5,1.5) 102(-2.5,1.5) 103(-1.5,1.5) 104(-0.5,1.5) 105(0.5,1.5) 106(1.5,1.5) 107(2.5,1.5) 108(3.5,1.5) 109(4.5,1.5) 110(5.5,1.5) 111(6.5,1.5) 112(7.5,1.5) 113(-7.5,0.5) 114(-6.5,0.5) 115(-5.5,0.5) 116(-4.5,0.5) 117(-3.5,0.5) 118(-2.5,0.5) 119(-1.5,0.5) 120(-0.5,0.5) 121(0.5,0.5) 122(1.5,0.5) 123(2.5,0.5) 124(3.5,0.5) 125(4.5,0.5) 126(5.5,0.5) 127(6.5,0.5) 128(7.5,0.5) 129(-7.5,-0.5) 130(-6.5,-0.5) 131(-5.5,-0.5) 132(-4.5,-0.5) 133(-3.5,-0.5) 134(-2.5,-0.5) 135(-1.5,-0.5) 136(-0.5,-0.5) 137(0.5,-0.5) 138(1.5,-0.5) 139(2.5,-0.5) 140(3.5,-0.5) 141(4.5,-0.5) 142(5.5,-0.5) 143(6.5,-0.5) 144(7.5,-0.5) 145(-7.5,-1.5) 146(-6.5,-1.5) 147(-5.5,-1.5) 148(-4.5,-1.5) 149(-3.5,-1.5) 150(-2.5,-1.5) 151(-1.5,-1.5) 152(-0.5,-1.5) 153(0.5,-1.5) 154(1.5,-1.5) 155(2.5,-1.5) 156(3.5,-1.5) 157(4.5,-1.5) 158(5.5,-1.5) 159(6.5,-1.5) 160(7.5,-1.5) 161(-7.5,-2.5) 162(-6.5,-2.5) 163(-5.5,-2.5) 164(-4.5,-2.5) 165(-3.5,-2.5) 166(-2.5,-2.5) 167(-1.5,-2.5) 168(-0.5,-2.5) 169(0.5,-2.5) 170(1.5,-2.5) 171(2.5,-2.5) 172(3.5,-2.5) 173(4.5,-2.5) 174(5.5,-2.5) 175(6.5,-2.5) 176(7.5,-2.5) 177(-7.5,-3.5) 178(-6.5,-3.5) 179(-5.5,-3.5) 180(-4.5,-3.5) 181(-3.5,-3.5) 182(-2.5,-3.5) 183(-1.5,-3.5) 184(-0.5,-3.5) 185(0.5,-3.5) 186(1.5,-3.5) 187(2.5,-3.5) 188(3.5,-3.5) 189(4.5,-3.5) 190(5.5,-3.5) 191(6.5,-3.5) 192(7.5,-3.5) 193(-7.5,-4.5) 194(-6.5,-4.5) 195(-5.5,-4.5) 196(-4.5,-4.5) 197(-3.5,-4.5) 198(-2.5,-4.5) 199(-1.5,-4.5) 200(-0.5,-4.5) 201(0.5,-4.5) 202(1.5,-4.5) 203(2.5,-4.5) 204(3.5,-4.5) 205(4.5,-4.5) 206(5.5,-4.5) 207(6.5,-4.5) 208(7.5,-4.5) 209(-7.5,-5.5) 210(-6.5,-5.5) 211(-5.5,-5.5) 212(-4.5,-5.5) 213(-3.5,-5.5) 214(-2.5,-5.5) 215(-1.5,-5.5) 216(-0.5,-5.5) 217(0.5,-5.5) 218(1.5,-5.5) 219(2.5,-5.5) 220(3.5,-5.5) 221(4.5,-5.5) 222(5.5,-5.5) 223(6.5,-5.5) 224(7.5,-5.5) 225(-7.5,-6.5) 226(-6.5,-6.5) 227(-5.5,-6.5) 228(-4.5,-6.5) 229(-3.5,-6.5) 230(-2.5,-6.5) 231(-1.5,-6.5) 232(-0.5,-6.5) 233(0.5,-6.5) 234(1.5,-6.5) 235(2.5,-6.5) 236(3.5,-6.5) 237(4.5,-6.5) 238(5.5,-6.5) 239(6.5,-6.5) 240(7.5,-6.5) 241(-7.5,-7.5) 242(-6.5,-7.5) 243(-5.5,-7.5) 244(-4.5,-7.5) 245(-3.5,-7.5) 246(-2.5,-7.5) 247(-1.5,-7.5) 248(-0.5,-7.5) 249(0.5,-7.5) 250(1.5,-7.5) 251(2.5,-7.5) 252(3.5,-7.5) 253(4.5,-7.5) 254(5.5,-7.5) 255(6.5,-7.5) 256(7.5,-7.5)
  silkscreen extent -9.4,-8.6 8.6,9.4, body extent -8.6,-8.6 8.6,8.6, height 1.61
BGA484-0.5 [mm]
  round 0.28 smd: 1(-5.25,-5.25) 2(-4.75,-5.25) 3(-4.25,-5.25) 4(-3.75,-5.25) 5(-3.25,-5.25) 6(-2.75,-5.25) 7(-2.25,-5.25) 8(-1.75,-5.25) 9(-1.25,-5.25) 10(-0.75,-5.25) 11(-0.25,-5.25) 12(0.25,-5.25) 13(0.75,-5.25) 14(1.25,-5.25) 15(1.75,-5.25) 16(2.25,-5.25) 17(2.75,-5.25) 18(3.25,-5.25) 19(3.75,-5.25) 20(4.25,-5.25) 21(4.75,-5.25) 22(5.25,-5.25) 23(-5.25,-4.75) 24(-4.75,-4.75) 25(-4.25,-4.75) 26(-3.75,-4.75) 27(-3.25,-4.75) 28(-2.75,-4.75) 29(-2.25,-4.75) 30(-1.75,-4.75) 31(-1.25,-4.75) 32(-0.75,-4.75) 33(-0.25,-4.75) 34(0.25,-4.75) 35(0.75,-4.75) 36(1.25,-4.75) 37(1.75,-4.75) 38(2.25,-4.75) 39(2.75,-4.75) 40(3.25,-4.75) 41(3.75,-4.75) 42(4.25,-4.75) 43(4.75,-4.75) 44(5.25,-4.75) 45(-5.25,-4.25) 46(-4.75,-4.25) 47(-4.25,-4.25) 48(-3.75,-4.25) 49(-3.25,-4.25) 50(-2.75,-4.25) 51(-2.25,-4.25) 52(-1.75,-4.25) 53(-1.25,-4.25) 54(-0.75,-4.25) 55(-0.25,-4.25) 56(0.25,-4.25) 57(0.75,-4.25) 58(1.25,-4.25) 59(1.75,-4.25) 60(2.25,-4.25) 61(2.75,-4.25) 62(3.25,-4.25) 63(3.75,-4.25) 64(4.25,-4.25) 65(4.75,-4.25) 66(5.25,-4.25) 67(-5.25,-3.75) 67(-5.25,-3.75) 68(-4.75,-3.75) 69(-4.25,-3.75) 70(-3.75,-3.75) 71(-3.25,-3.75) 72(-2.75,-3.75) 73(-2.25,-3.75) 74(-1.75,-3.75) 75(-1.25,-3.75) 76(-0.75,-3.75) 77(-0.25,-3.75) 78(0.25,-3.75) 79(0.75,-3.75) 80(1.25,-3.75) 81(1.75,-3.75) 82(2.25,-3.75) 83(2.75,-3.75) 84(3.25,-3.75) 85(3.75,-3.75) 86(4.25,-3.75) 87(4.75,-3.75) 88(5.25,-3.75) 89(-5.25,-3.25) 89(-5.25,-3.25) 90(-4.75,-3.25) 91(-4.25,-3.25) 92(-3.75,-3.25) 93(-3.25,-3.25) 94(-2.75,-3.25) 95(-2.25,-3.25) 96(-1.75,-3.25) 97(-1.25,-3.25) 98(-0.75,-3.25) 99(-0.25,-3.25) 100(0.25,-3.25) 101(0.75,-3.25) 102(1.25,-3.25) 103(1.75,-3.25) 104(2.25,-3.25) 105(2.75,-3.25) 106(3.25,-3.25) 107(3.75,-3.25) 108(4.25,-3.25) 109(4.75,-3.25) 110(5.25,-3.25) 111(-5.25,-2.75) 112(-4.75,-2.75) 113(-4.25,-2.75) 114(-3.75,-2.75) 115(-3.25,-2.75) 116(-2.75,-2.75) 117(-2.25,-2.75) 118(-1.75,-2.75) 119(-1.25,-2.75) 120(-0.75,-2.75) 121(-0.25,-2.75) 122(0.25,-2.75) 123(0.75,-2.75) 124(1.25,-2.75) 125(1.75,-2.75) 126(2.25,-2.75) 127(2.75,-2.75) 128(3.25,-2.75) 129(3.75,-2.75) 130(4.25,-2.75) 131(4.75,-2.75) 132(5.25,-2.75) 133(-5.25,-2.25) 134(-4.75,-2.25) 135(-4.25,-2.25) 136(-3.75,-2.25) 137(-3.25,-2.25) 138(-2.75,-2.25) 139(-2.25,-2.25) 140(-1.75,-2.25) 141(-1.25,-2.25) 142(-0.75,-2.25) 143(-0.25,-2.25) 144(0.25,-2.25) 145(0.75,-2.25) 146(1.25,-2.25) 147(1.75,-2.25) 148(2.25,-2.25) 149(2.75,-2.25) 150(3.25,-2.25) 151(3.75,-2.25) 152(4.25,-2.25) 153(4.75,-2.25) 154(5.25,-2.25) 155(-5.25,-1.75) 156(-4.75,-1.75) 157(-4.25,-1.75) 158(-3.75,-1.75) 159(-3.25,-1.75) 160(-2.75,-1.75) 161(-2.25,-1.75) 162(-1.75,-1.75) 163(-1.25,-1.75) 164(-0.75,-1.75) 165(-0.25,-1.75) 166(0.25,-1.75) 167(0.75,-1.75) 168(1.25,-1.75) 169(1.75,-1.75) 170(2.25,-1.75) 171(2.75,-1.75) 172(3.25,-1.75) 173(3.75,-1.75) 174(4.25,-1.75) 175(4.75,-1.75) 176(5.25,-1.75) 177(-5.25,-1.25) 178(-4.75,-1.25) 179(-4.25,-1.25) 180(-3.75,-1.25) 181(-3.25,-1.25) 182(-2.75,-1.25) 183(-2.25,-1.25) 184(-1.75,-1.25) 185(-1.25,-1.25) 186(-0.75,-1.25) 187(-0.25,-1.25) 188(0.25,-1.25) 189(0.75,-1.25) 190(1.25,-1.25) 191(1.75,-1.25) 192(2.25,-1.25) 193(2.75,-1.25) 194(3.25,-1.25) 195(3.75,-1.25) 196(4.25,-1.25) 197(4.75,-1.25) 198(5.25,-1.25) 199(-5.25,-0.75) 200(-4.75,-0.75) 201(-4.25,-0.75) 202(-3.75,-0.75) 203(-3.25,-0.75) 204(-2.75,-0.75) 205(-2.25,-0.75) 206(-1.75,-0.75) 207(-1.25,-0.75) 208(-0.75,-0.75) 209(-0.25,-0.75) 210(0.25,-0.75) 211(0.75,-0.75) 212(1.25,-0.75) 213(1.75,-0.75) 214(2.25,-0.75) 215(2.75,-0.75) 216(3.25,-0.75) 217(3.75,-0.75) 218(4.25,-0.75) 219(4.75,-0.75) 220(5.25,-0.75) 221(-5.25,-0.25) 222(-4.75,-0.25) 223(-4.25,-0.25) 224(-3.75,-0.25) 225(-3.25,-0.25) 226(-2.75,-0.25) 227(-2.25,-0.25) 228(-1.75,-0.25) 229(-1.25,-0.25) 230(-0.75,-0.25) 231(-0.25,-0.25) 232(0.25,-0.25) 233(0.75,-0.25) 234(1.25,-0.25) 235(1.75,-0.25) 236(2.25,-0.25) 237(2.75,-0.25) 238(3.25,-0.25) 239(3.75,-0.25) 240(4.25,-0.25) 241(4.75,-0.25) 242(5.25,-0.25) 243(-5.25,0.25) 244(-4.75,0.25) 245(-4.25,0.25) 246(-3.75,0.25) 247(-3.25,0.25) 248(-2.75,0.25) 249(-2.25,0.25) 250(-1.75,0.25) 251(-1.25,0.25) 252(-0.75,0.25) 253(-0.25,0.25) 254(0.25,0.25) 255(0.75,0.25) 256(1.25,0.25) 257(1.75,0.25) 258(2.25,0.25) 259(2.75,0.25) 260(3.25,0.25) 261(3.75,0.25) 262(4.25,0.25) 263(4.75,0.25) 264(5.25,0.25) 265(-5.25,0.75) 266(-4.75,0.75) 267(-4.25,0.75) 268(-3.75,0.75) 269(-3.25,0.75) 270(-2.75,0.75) 271(-2.25,0.75) 272(-1.75,0.75) 273(-1.25,0.75) 274(-0.75,0.75) 275(-0.25,0.75) 276(0.25,0.75) 277(0.75,0.75) 278(1.25,0.75) 279(1.75,0.75) 280(2.25,0.75) 281(2.75,0.75) 282(3.25,0.75) 283(3.75,0.75) 284(4.25,0.75) 285(4.75,0.75) 286(5.25,0.75) 287(-5.25,1.25) 288(-4.75,1.25) 289(-4.25,1.25) 290(-3.75,1.25) 291(-3.25,1.25) 292(-2.75,1.25) 293(-2.25,1.25) 294(-1.75,1.25) 295(-1.25,1.25) 296(-0.75,1.25) 297(-0.25,1.25) 298(0.25,1.25) 299(0.75,1.25) 300(1.25,1.25) 301(1.75,1.25) 302(2.25,1.25) 303(2.75,1.25) 304(3.25,1.25) 305(3.75,1.25) 306(4.25,1.25) 307(4.75,1.25) 308(5.25,1.25) 309(-5.25,1.75) 310(-4.75,1.75) 311(-4.25,1.75) 312(-3.75,1.75) 313(-3.25,1.75) 314(-2.75,1.75) 315(-2.25,1.75) 316(-1.75,1.75) 317(-1.25,1.75) 318(-0.75,1.75) 319(-0.25,1.75) 320(0.25,1.75) 321(0.75,1.75) 322(1.25,1.75) 323(1.75,1.75) 324(2.25,1.75) 325(2.75,1.75) 326(3.25,1.75) 327(3.75,1.75) 328(4.25,1.75) 329(4.75,1.75) 330(5.25,1.75) 331(-5.25,2.25) 332(-4.75,2.25) 333(-4.25,2.25) 334(-3.75,2.25) 335(-3.25,2.25) 336(-2.75,2.25) 337(-2.25,2.25) 338(-1.75,2.25) 339(-1.25,2.25) 340(-0.75,2.25) 341(-0.25,2.25) 342(0.25,2.25) 343(0.75,2.25) 344(1.25,2.25) 345(1.75,2.25) 346(2.25,2.25) 347(2.75,2.25) 348(3.25,2.25) 349(3.75,2.25) 350(4.25,2.25) 351(4.75,2.25) 352(5.25,2.25) 353(-5.25,2.75) 354(-4.75,2.75) 355(-4.25,2.75) 356(-3.75,2.75) 357(-3.25,2.75) 358(-2.75,2.75) 359(-2.25,2.75) 360(-1.75,2.75) 361(-1.25,2.75) 362(-0.75,2.75) 363(-0.25,2.75) 364(0.25,2.75) 365(0.75,2.75) 366(1.25,2.75) 367(1.75,2.75) 368(2.25,2.75) 369(2.75,2.75) 370(3.25,2.75) 371(3.75,2.75) 372(4.25,2.75) 373(4.75,2.75) 374(5.25,2.75) 375(-5.25,3.25) 376(-4.75,3.25) 377(-4.25,3.25) 378(-3.75,3.25) 379(-3.25,3.25) 380(-2.75,3.25) 381(-2.25,3.25) 382(-1.75,3.25) 383(-1.25,3.25) 384(-0.75,3.25) 385(-0.25,3.25) 386(0.25,3.25) 387(0.75,3.25) 388(1.25,3.25) 389(1.75,3.25) 390(2.25,3.25) 391(2.75,3.25) 392(3.25,3.25) 393(3.75,3.25) 394(4.25,3.25) 395(4.75,3.25) 396(5.25,3.25) 397(-5.25,3.75) 398(-4.75,3.75) 399(-4.25,3.75) 400(-3.75,3.75) 401(-3.25,3.75) 402(-2.75,3.75) 403(-2.25,3.75) 404(-1.75,3.75) 405(-1.25,3.75) 406(-0.75,3.75) 407(-0.25,3.75) 408(0.25,3.75) 409(0.75,3.75) 410(1.25,3.75) 411(1.75,3.75) 412(2.25,3.75) 413(2.75,3.75) 414(3.25,3.75) 415(3.75,3.75) 416(4.25,3.75) 417(4.75,3.75) 418(5.25,3.75) 419(-5.25,4.25) 420(-4.75,4.25) 421(-4.25,4.25) 422(-3.75,4.25) 423(-3.25,4.25) 424(-2.75,4.25) 425(-2.25,4.25) 426(-1.75,4.25) 427(-1.25,4.25) 428(-0.75,4.25) 429(-0.25,4.25) 430(0.25,4.25) 431(0.75,4.25) 432(1.25,4.25) 433(1.75,4.25) 434(2.25,4.25) 435(2.75,4.25) 436(3.25,4.25) 437(3.75,4.25) 438(4.25,4.25) 439(4.75,4.25) 440(5.25,4.25) 441(-5.25,4.75) 442(-4.75,4.75) 443(-4.25,4.75) 444(-3.75,4.75) 445(-3.25,4.75) 446(-2.75,4.75) 447(-2.25,4.75) 448(-1.75,4.75) 449(-1.25,4.75) 450(-0.75,4.75) 451(-0.25,4.75) 452(0.25,4.75) 453(0.75,4.75) 454(1.25,4.75) 455(1.75,4.75) 456(2.25,4.75) 457(2.75,4.75) 458(3.25,4.75) 459(3.75,4.75) 460(4.25,4.75) 461(4.75,4.75) 462(5.25,4.75) 463(-5.25,5.25) 464(-4.75,5.25) 465(-4.25,5.25) 466(-3.75,5.25) 467(-3.25,5.25) 468(-2.75,5.25) 469(-2.25,5.25) 470(-1.75,5.25) 471(-1.25,5.25) 472(-0.75,5.25) 473(-0.25,5.25) 474(0.25,5.25) 475(0.75,5.25) 476(1.25,5.25) 477(1.75,5.25) 478(2.25,5.25) 479(2.75,5.25) 480(3.25,5.25) 481(3.75,5.25) 482(4.25,5.25) 483(4.75,5.25) 484(5.25,5.25)
  silkscreen extent -6.85,-6 6,6.85, body extent -6,-6 6,6, height 1.45
DIN41612 [mm]
  round 1.75 hole 1.1: 1(-19.05,2.54) 2(-16.51,2.54) 3(-13.97,2.54) 4(-11.43,2.54) 5(-8.89,2.54) 6(-6.35,2.54) 7(-3.81,2.54) 8(-1.27,2.54) 9(1.27,2.54) 10(3.81,2.54) 11(6.35,2.54) 12(8.89,2.54) 13(11.43,2.54) 14(13.97,2.54) 15(16.51,2.54) 16(19.05,2.54) 17(-19.05,0) 18(-16.51,0) 19(-13.97,0) 20(-11.43,0) 21(-8.89,0) 22(-6.35,0) 23(-3.81,0) 24(-1.27,0) 25(1.27,0) 26(3.81,0) 27(6.35,0) 28(8.89,0) 29(11.43,0) 30(13.97,0) 31(16.51,0) 32(19.05,0) 33(-19.05,-2.54) 34(-16.51,-2.54) 35(-13.97,-2.54) 36(-11.43,-2.54) 37(-8.89,-2.54) 38(-6.35,-2.54) 39(-3.81,-2.54) 40(-1.27,-2.54) 41(1.27,-2.54) 42(3.81,-2.54) 43(6.35,-2.54) 44(8.89,-2.54) 45(11.43,-2.54) 46(13.97,-2.54) 47(16.51,-2.54) 48(19.05,-2.54)
  round 2.2 hole 2.8 unplated: ""(-24.68,0.3) ""(24.68,0.3)
  silkscreen extent -26.8,-5.5 26.8,5.4, body extent -26.61,-5.3 26.61,5.3, height 11.5
DPAK [mm]
  rect 5.8x6.2 smd: 1(0,1.5)
  rect 1.6x3 smd: 2(2.285,-5.71) 3(-2.285,-5.71)
  silkscreen extent -3.4,-4.5 3.4,4, body extent -3.34,-6.2 3.39,3.9, height 2.37
FID#1 [mm]
  round 1 smd paste-1 mask+0.5: 1(0,0)
FID#2 [mm]
  round 1 smd paste-1 mask+0.5: 1(6.175,2.325)
FID#3 [mm]
  round 1 smd paste-1 mask+0.5: 1(4.575,-0.825)
PL40_0.8 [mm]
  rect 0.5x2 smd: 1(-7.6,2.2) 2(-6.8,2.2) 3(-6,2.2) 4(-5.2,2.2) 5(-4.4,2.2) 6(-3.6,2.2) 7(-2.8,2.2) 8(-2,2.2) 9(-1.2,2.2) 10(-0.4,2.2) 11(0.4,2.2) 12(1.2,2.2) 13(2,2.2) 14(2.8,2.2) 15(3.6,2.2) 16(4.4,2.2) 17(5.2,2.2) 18(6,2.2) 19(6.8,2.2) 20(7.6,2.2) 21(-7.6,-2.2) 22(-6.8,-2.2) 23(-6,-2.2) 24(-5.2,-2.2) 25(-4.4,-2.2) 26(-3.6,-2.2) 27(-2.8,-2.2) 28(-2,-2.2) 29(-1.2,-2.2) 30(-0.4,-2.2) 31(0.4,-2.2) 32(1.2,-2.2) 33(2,-2.2) 34(2.8,-2.2) 35(3.6,-2.2) 36(4.4,-2.2) 37(5.2,-2.2) 38(6,-2.2) 39(6.8,-2.2) 40(7.6,-2.2)
  round 0.8 hole 0.8 unplated: ""(-10.1,0)
  round 1.2 hole 1.2 unplated: ""(10.1,0)
  silkscreen extent -11,-3.5 11,3.5, body extent -10.9,-3 10.9,3, height 6.65
PLCC44 [mm]
  rrect100% 0.61x2.2 smd: 1(-6.35,-8.1) 2(-5.08,-8.1) 3(-3.81,-8.1) 4(-2.54,-8.1) 5(-1.27,-8.1) 6(0,-8.1) 7(1.27,-8.1) 8(2.54,-8.1) 9(3.81,-8.1) 10(5.08,-8.1) 11(6.35,-8.1) 23(6.35,8.1) 24(5.08,8.1) 25(3.81,8.1) 26(2.54,8.1) 27(1.27,8.1) 28(0,8.1) 29(-1.27,8.1) 30(-2.54,8.1) 31(-3.81,8.1) 32(-5.08,8.1) 33(-6.35,8.1)
  rrect100% 2.2x0.61 smd: 12(8.1,-6.355) 13(8.1,-5.085) 14(8.1,-3.815) 15(8.1,-2.545) 16(8.1,-1.275) 17(8.1,-0.005) 18(8.1,1.265) 19(8.1,2.535) 20(8.1,3.805) 21(8.1,5.075) 22(8.1,6.345) 34(-8.1,6.34) 35(-8.1,5.07) 36(-8.1,3.8) 37(-8.1,2.53) 38(-8.1,1.26) 39(-8.1,-0.01) 40(-8.1,-1.28) 41(-8.1,-2.55) 42(-8.1,-3.82) 43(-8.1,-5.09) 44(-8.1,-6.36)
  silkscreen extent -9.6,-8.8 8.8,9.6, body extent -8.8,-8.8 8.8,8.8, height 4.3
"PLD 2x10" [mm]
  round 1.85 hole 1.2: 1(-11.43,1.27) 2(-8.89,1.27) 3(-6.35,1.27) 4(-3.81,1.27) 5(-1.27,1.27) 6(1.27,1.27) 7(3.81,1.27) 8(6.35,1.27) 9(8.89,1.27) 10(11.43,1.27) 11(-11.43,-1.27) 12(-8.89,-1.27) 13(-6.35,-1.27) 14(-3.81,-1.27) 15(-1.27,-1.27) 16(1.27,-1.27) 17(3.81,-1.27) 18(6.35,-1.27) 19(8.89,-1.27) 20(11.43,-1.27)
  silkscreen extent -12.9,-2.8 13,2.8, body extent -12.64,-2.54 12.76,2.54, height 8.54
